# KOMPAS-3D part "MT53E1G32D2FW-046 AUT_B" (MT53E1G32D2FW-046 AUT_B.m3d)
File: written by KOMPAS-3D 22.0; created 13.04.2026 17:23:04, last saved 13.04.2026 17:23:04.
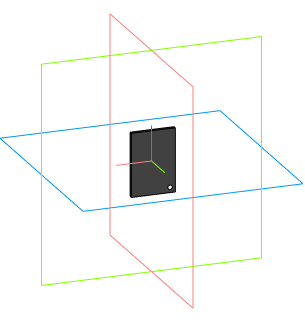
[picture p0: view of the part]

Document properties: Автор: Andrey; Полное имя файла: C:\Users\User1\Documents\MT53E1G32D2FW-046 AUT_B.m3d

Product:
- Part/product: MT53E1G32D2FW-046 AUT_B

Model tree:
1. Операция без истории:1
2. Операция без истории:2
3. Операция без истории:3
4. Операция без истории:4
5. Операция без истории:5
6. Операция без истории:6
7. Операция без истории:7
8. Операция без истории:8
9. Операция без истории:9
10. Операция без истории:10
11. Операция без истории:11
12. Операция без истории:12
13. Операция без истории:13
14. Операция без истории:14
15. Операция без истории:15
16. Операция без истории:16
17. Операция без истории:17
18. Операция без истории:18
19. Операция без истории:19
20. Операция без истории:20
21. Операция без истории:21
22. Операция без истории:22
23. Операция без истории:23
24. Операция без истории:24
25. Операция без истории:25
26. Операция без истории:26
27. Операция без истории:27
28. Операция без истории:28
29. Операция без истории:29
30. Операция без истории:30
31. Операция без истории:31
32. Операция без истории:32
33. Операция без истории:33
34. Операция без истории:34
35. Операция без истории:35
36. Операция без истории:36
37. Операция без истории:37
38. Операция без истории:38
39. Операция без истории:39
40. Операция без истории:40
41. Операция без истории:41
42. Операция без истории:42
43. Операция без истории:43
44. Операция без истории:44
45. Операция без истории:45
46. Операция без истории:46
47. Операция без истории:47
48. Операция без истории:48
49. Операция без истории:49
50. Операция без истории:50
51. Операция без истории:51
52. Операция без истории:52
53. Операция без истории:53
54. Операция без истории:54
55. Операция без истории:55
56. Операция без истории:56
57. Операция без истории:57
58. Операция без истории:58
59. Операция без истории:59
60. Операция без истории:60
61. Операция без истории:61
62. Операция без истории:62
63. Операция без истории:63
64. Операция без истории:64
65. Операция без истории:65
66. Операция без истории:66
67. Операция без истории:67
68. Операция без истории:68
69. Операция без истории:69
70. Операция без истории:70
71. Операция без истории:71
72. Операция без истории:72
73. Операция без истории:73
74. Операция без истории:74
75. Операция без истории:75
76. Операция без истории:76
77. Операция без истории:77
78. Операция без истории:78
79. Операция без истории:79
80. Операция без истории:80
81. Операция без истории:81
82. Операция без истории:82
83. Операция без истории:83
84. Операция без истории:84
85. Операция без истории:85
86. Операция без истории:86
87. Операция без истории:87
88. Операция без истории:88
89. Операция без истории:89
90. Операция без истории:90
91. Операция без истории:91
92. Операция без истории:92
93. Операция без истории:93
94. Операция без истории:94
95. Операция без истории:95
96. Операция без истории:96
97. Операция без истории:97
98. Операция без истории:98
99. Операция без истории:99
100. Операция без истории:100
101. Операция без истории:101
102. Операция без истории:102
103. Операция без истории:103
104. Операция без истории:104
105. Операция без истории:105
106. Операция без истории:106
107. Операция без истории:107
108. Операция без истории:108
109. Операция без истории:109
110. Операция без истории:110
111. Операция без истории:111
112. Операция без истории:112
113. Операция без истории:113
114. Операция без истории:114
115. Операция без истории:115
116. Операция без истории:116
117. Операция без истории:117
118. Операция без истории:118
119. Операция без истории:119
120. Операция без истории:120
121. Операция без истории:121
122. Операция без истории:122
123. Операция без истории:123
124. Операция без истории:124
125. Операция без истории:125
126. Операция без истории:126
127. Операция без истории:127
128. Операция без истории:128
129. Операция без истории:129
130. Операция без истории:130
131. Операция без истории:131
132. Операция без истории:132
133. Операция без истории:133
134. Операция без истории:134
135. Операция без истории:135
136. Операция без истории:136
137. Операция без истории:137
138. Операция без истории:138
139. Операция без истории:139
140. Операция без истории:140
141. Операция без истории:141
142. Операция без истории:142
143. Операция без истории:143
144. Операция без истории:144
145. Операция без истории:145
146. Операция без истории:146
147. Операция без истории:147
148. Операция без истории:148
149. Операция без истории:149
150. Операция без истории:150
151. Операция без истории:151
152. Операция без истории:152
153. Операция без истории:153
154. Операция без истории:154
155. Операция без истории:155
156. Операция без истории:156
157. Операция без истории:157
158. Операция без истории:158
159. Операция без истории:159
160. Операция без истории:160
161. Операция без истории:161
162. Операция без истории:162
163. Операция без истории:163
164. Операция без истории:164
165. Операция без истории:165
166. Операция без истории:166
167. Операция без истории:167
168. Операция без истории:168
169. Операция без истории:169
170. Операция без истории:170
171. Операция без истории:171
172. Операция без истории:172
173. Операция без истории:173
174. Операция без истории:174
175. Операция без истории:175
176. Операция без истории:176
177. Операция без истории:177
178. Операция без истории:178
179. Операция без истории:179
180. Операция без истории:180
181. Операция без истории:181
182. Операция без истории:182
183. Операция без истории:183
184. Операция без истории:184
185. Операция без истории:185
186. Операция без истории:186
187. Операция без истории:187
188. Операция без истории:188
189. Операция без истории:189
190. Операция без истории:190
191. Операция без истории:191
192. Операция без истории:192
193. Операция без истории:193
194. Операция без истории:194
195. Операция без истории:195
196. Операция без истории:196
197. Операция без истории:197
198. Операция без истории:198
199. Операция без истории:199
200. Операция без истории:200
201. Операция без истории:201
202. Операция без истории:202
203. Операция без истории:203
